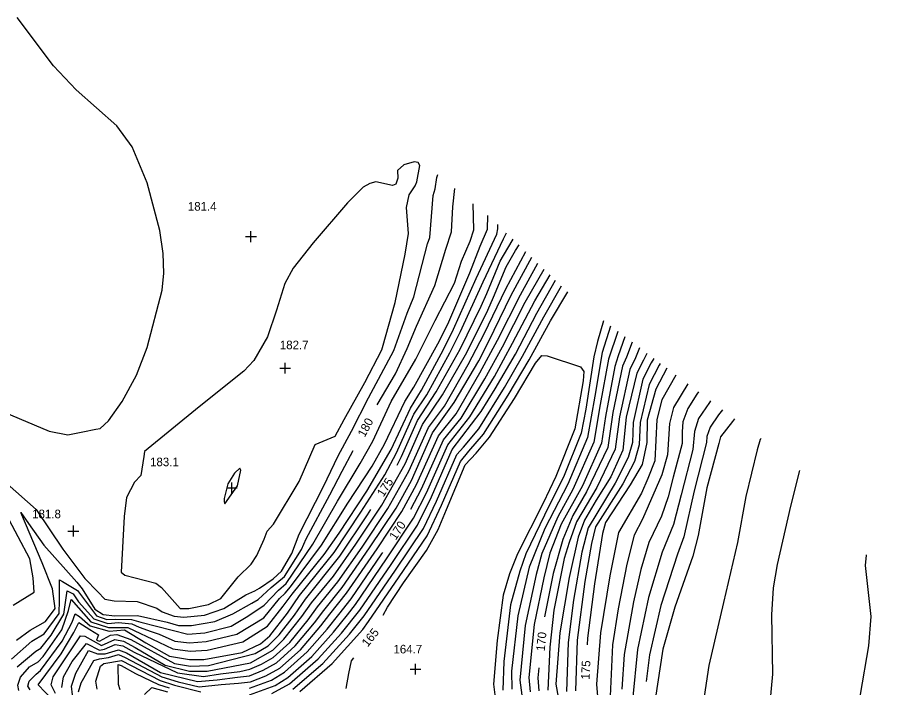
# Model space of a CAD drawing. Extents: x 1467615 to 2003689, y 770235 to 1108726.
# Drawn here: x 1996139.1 to 1996343.1, y 777293.4 to 777449.4 of the extents above; entities that cross this region are included whole.
import ezdxf

# ---------------------------------------------------------------- set-up
doc = ezdxf.new("R2010")
doc.units = 0
for name, color, linetype in [('RD_DTM_Major1', 7, 'Continuous'), ('RD_DTM_Major1_Lbl', 7, 'Continuous'), ('RD_DTM_Minor1', 7, 'Continuous'), ('RD_DTM_Spot_Elev', 7, 'Continuous')]:
    doc.layers.add(name, color=color, linetype=linetype)

msp = doc.modelspace()

# ---------------------------------------------------------------- linework, layer by layer
at = {"layer": 'RD_DTM_Major1'}
for points in [[(1996222.86, 777359.2), (1996227.12, 777366.41), (1996229.82, 777372.33), (1996232.01, 777377.55), (1996236.28, 777387.01), (1996238.85, 777395.49), (1996240.14, 777399.47), (1996240.48, 777405.34), (1996240.94, 777409.57)], [(1996227.5, 777345.19), (1996228.51, 777347.2), (1996232.22, 777355.58), (1996236.62, 777362.24), (1996242.21, 777372.2), (1996247.1, 777382.2), (1996248.39, 777385.16), (1996251.46, 777392.7), (1996254.3, 777397.39), (1996254.51, 777397.79)], [(1996230.66, 777334.93), (1996233.15, 777339.7), (1996238.31, 777351.1), (1996242.45, 777356.13), (1996247.89, 777365.3), (1996252.05, 777372.74), (1996257.34, 777383.14), (1996261.72, 777390.84)], [(1996282.2, 777373.79), (1996280.91, 777370.34), (1996280.01, 777368.24), (1996277.76, 777357.48), (1996276.53, 777349.26), (1996271.57, 777338.97), (1996268.39, 777333.49), (1996266.05, 777327.89), (1996263.83, 777320), (1996261.81, 777309.91)], [(1996224.26, 777310.25), (1996225.23, 777312.16), (1996228.95, 777317.79), (1996234.35, 777325.32), (1996237.07, 777330.21), (1996238.96, 777334.9), (1996243.38, 777345.26), (1996245.91, 777348.01), (1996249.03, 777351.7), (1996254.82, 777360.7), (1996259.69, 777368.92), (1996261.17, 777370.71), (1996262.43, 777370.63), (1996270.23, 777368.05), (1996270.98, 777366.96), (1996270.81, 777364.83), (1996268.89, 777353.65), (1996264.48, 777342.58), (1996261.54, 777336.34), (1996255.56, 777324.51), (1996253.68, 777319.91), (1996252.22, 777314.96), (1996250.81, 777304.36), (1996249.96, 777294.21), (1996250.44, 777290.47)], [(1996290.29, 777367.75), (1996287.7, 777362.89), (1996285.69, 777355.68), (1996285.66, 777350.46), (1996284.56, 777345.33), (1996281.76, 777340.61), (1996275.99, 777331.87), (1996275.29, 777329.29), (1996273.43, 777317.53), (1996271.8, 777304.94), (1996271.72, 777303.35)], [(1996303.26, 777358.07), (1996302.33, 777356.9), (1996300.37, 777354.06), (1996299.63, 777351.87), (1996299.56, 777350.49), (1996296.65, 777339.19), (1996294.29, 777328.5), (1996292.77, 777324.5), (1996288.94, 777312.53), (1996286.24, 777301.02), (1996285.48, 777294.83)], [(1996138.87, 777304.46), (1996142.07, 777306.78), (1996145.61, 777308.78), (1996147.84, 777311.79), (1996147.28, 777316.41), (1996144.82, 777322.48), (1996140.95, 777331.57), (1996139.89, 777334.15), (1996141.64, 777331.59), (1996145.21, 777326.58), (1996152.93, 777317.94), (1996154.16, 777316.4), (1996157.11, 777311.65), (1996159.03, 777310.4), (1996161.76, 777310.12), (1996167.05, 777310.17), (1996173.99, 777308.65), (1996176.56, 777307.88), (1996179.66, 777307.88), (1996185.08, 777308.81), (1996189.21, 777310.57), (1996193.64, 777313.03), (1996195.18, 777313.94), (1996198.19, 777316.7), (1996201.24, 777319.28), (1996205.26, 777325.52), (1996206.34, 777328), (1996211.85, 777338.26), (1996214.69, 777343.8), (1996217.24, 777348.59)], [(1996150.46, 777287.23), (1996143.91, 777294.05), (1996149.27, 777301.28), (1996152.21, 777306.22), (1996153.39, 777308.57), (1996155.91, 777306.91), (1996157.93, 777305.71), (1996157.47, 777304.43), (1996158.22, 777304.19), (1996160.73, 777305.64), (1996162.2, 777305.75), (1996165.52, 777304.64), (1996175.68, 777299.03), (1996179.36, 777298.41), (1996183.57, 777298.53), (1996194.42, 777301.34), (1996197.47, 777303.1), (1996200.06, 777305.67), (1996203.6, 777310.29), (1996206.16, 777313.99), (1996214.13, 777323.97), (1996220.57, 777333.62), (1996221.37, 777334.87)], [(1996193.16, 777293.24), (1996198.26, 777295.12), (1996201.27, 777296.97), (1996206.58, 777301.73), (1996211.21, 777307.03), (1996213.92, 777310.45), (1996216.76, 777314.07), (1996223.95, 777324.53), (1996224.16, 777324.85)], [(1996215.66, 777293.23), (1996216.22, 777296.66), (1996216.85, 777299.62), (1996217.44, 777300.34)], [(1996157.66, 777293.03), (1996157.36, 777294.87), (1996158.4, 777298.4), (1996159.17, 777299), (1996163.35, 777299.69), (1996172.32, 777295.03), (1996175.67, 777293.96), (1996181.76, 777292.44)], [(1996260.47, 777297.98), (1996260.24, 777295.65), (1996260.53, 777292.62)]]:
    msp.add_lwpolyline(points, dxfattribs=at)
at = {"layer": 'RD_DTM_Minor1'}
for points in [[(1996136, 777357.5), (1996146.46, 777353.11), (1996150.83, 777352.27), (1996154.33, 777352.98), (1996157.36, 777353.55), (1996158.33, 777353.73), (1996160.31, 777355.49), (1996163.51, 777359.98), (1996166.84, 777366.12), (1996169.26, 777372.54), (1996172.77, 777385.89), (1996173.18, 777389.88), (1996173.05, 777394.49), (1996172.26, 777399.81), (1996169.32, 777410.89), (1996165.82, 777419.27), (1996162.21, 777424.21), (1996152.77, 777432.55), (1996147.5, 777438.16), (1996139.05, 777449.39)], [(1996224.07, 777372.61), (1996227.05, 777383.05), (1996229.4, 777394.28), (1996230.12, 777399.12), (1996229.68, 777405.15), (1996230.3, 777408.08), (1996231.73, 777410.21), (1996232.08, 777411.17), (1996232.77, 777414.95), (1996232.37, 777415.65), (1996231.47, 777415.83), (1996229.07, 777415.09), (1996227.62, 777413.8), (1996227.64, 777411.98), (1996227.18, 777410.56), (1996226.43, 777410.32), (1996222.51, 777411.12), (1996221.18, 777410.77), (1996219.63, 777409.88), (1996215.94, 777406.28), (1996207.96, 777396.92), (1996203.33, 777391.03), (1996201.34, 777387.44), (1996199.39, 777381.27), (1996197.31, 777375.04), (1996194.13, 777369.52), (1996191.83, 777367.09), (1996181.42, 777358.74), (1996168.7, 777348.36), (1996168.52, 777347.18), (1996167.81, 777342.81), (1996166.38, 777341.21), (1996164.49, 777337.69), (1996163.91, 777333.24), (1996163.27, 777320.3), (1996164.1, 777319.6), (1996171.35, 777317.7), (1996172.66, 777316.68), (1996176.97, 777311.85), (1996178.97, 777311.82), (1996183.59, 777312.74), (1996186.44, 777314.15), (1996188.31, 777316.44), (1996190.51, 777319.21), (1996193.51, 777322.11), (1996194.87, 777324.13), (1996196.57, 777327.97), (1996197.24, 777329.82), (1996198.7, 777331.47), (1996204.7, 777341.37), (1996208.44, 777349.99), (1996213.07, 777351.95), (1996215.16, 777355.84), (1996220.01, 777364.43), (1996223.91, 777372.06), (1996224.07, 777372.61)], [(1996136.72, 777340.87), (1996143.49, 777334.84), (1996149.66, 777325.67), (1996154.81, 777318.84), (1996157.84, 777315.68), (1996159.42, 777314.01), (1996161.62, 777313.59), (1996166.96, 777313.47), (1996171.55, 777311.91), (1996172.81, 777311.04), (1996175.58, 777310.04), (1996177.86, 777309.78), (1996182.68, 777310.26), (1996187.12, 777311.86), (1996192.3, 777314.99), (1996194.33, 777315.9), (1996195.44, 777316.55), (1996198.62, 777318.72), (1996200.56, 777320.54), (1996203, 777324.6), (1996204.67, 777329.13), (1996210.35, 777340.2), (1996212.07, 777343.82), (1996213.76, 777347.36), (1996216.9, 777353.12), (1996220.83, 777360.83), (1996226.74, 777371.87), (1996229.83, 777380.56), (1996231.38, 777384.38), (1996234.6, 777396.7), (1996235.08, 777398.2), (1996235.86, 777407.93), (1996236.35, 777409.48), (1996236.77, 777412.14), (1996236.95, 777412.85)], [(1996137.74, 777300.01), (1996142.44, 777304.23), (1996145.33, 777305.95), (1996148.81, 777310.69), (1996148.87, 777313.73), (1996148.85, 777318.53), (1996149.58, 777318.11), (1996153.04, 777315.98), (1996157.52, 777310.11), (1996159.89, 777309.27), (1996161.95, 777309.32), (1996165.65, 777309.26), (1996167.83, 777308.65), (1996178.78, 777305.85), (1996182.74, 777306.14), (1996188.85, 777307.7), (1996192.73, 777310.07), (1996196.57, 777312.61), (1996199.91, 777316.1), (1996201.65, 777317.66), (1996207.87, 777326.82), (1996213.62, 777336.78), (1996218.92, 777345.57), (1996221.88, 777350.81), (1996226.09, 777359.99), (1996231.84, 777369.87), (1996236.37, 777378.84), (1996240.87, 777387.54), (1996242.52, 777392.64), (1996244.53, 777397.36), (1996245.33, 777399.95), (1996245.23, 777406.05)], [(1996139, 777298.25), (1996143.38, 777301.92), (1996144.51, 777302.56), (1996146.94, 777305.58), (1996149.86, 777310.53), (1996150.68, 777315.92), (1996152.08, 777315.26), (1996153.3, 777313.39), (1996156.85, 777309.41), (1996160.13, 777308.3), (1996162.63, 777308.55), (1996165.72, 777308.23), (1996167.42, 777307.49), (1996170.26, 777306.46), (1996172.13, 777305.86), (1996175.74, 777304.25), (1996179.19, 777303.86), (1996183.01, 777304.13), (1996190.16, 777305.86), (1996196.49, 777309.66), (1996200.13, 777314.16), (1996201.42, 777315.36), (1996202.69, 777316.85), (1996209.88, 777326.53), (1996216.04, 777336.32), (1996221.66, 777344.93), (1996224.53, 777350.09), (1996229.3, 777360.03), (1996231.4, 777363.38), (1996236.98, 777373.46), (1996239.27, 777378.03), (1996244.43, 777389.93), (1996246.86, 777396.2), (1996248.57, 777400.09), (1996248.6, 777403.28)], [(1996139.44, 777292.7), (1996139.15, 777293.94), (1996139.77, 777295.86), (1996141.88, 777298.21), (1996143.9, 777299.43), (1996145.06, 777300.63), (1996149.4, 777306.83), (1996151.02, 777311.35), (1996151.63, 777313.94), (1996156.18, 777308.71), (1996160.29, 777307.38), (1996164.81, 777307.43), (1996171.98, 777304.01), (1996175.24, 777302.47), (1996179.34, 777301.88), (1996183.27, 777302.12), (1996191.55, 777304.08), (1996197.35, 777307.72), (1996200.99, 777312.38), (1996203.06, 777315.15), (1996210.51, 777324.42), (1996213.99, 777329.39), (1996220.42, 777339.14), (1996226.13, 777348.85), (1996230.59, 777358.47), (1996233.2, 777362.68), (1996238.26, 777372.1), (1996240.64, 777376.86), (1996245.88, 777388.65), (1996250.68, 777398.94), (1996250.94, 777400.23), (1996250.94, 777401.23)], [(1996142.03, 777292.88), (1996141.53, 777293.74), (1996141.83, 777294.94), (1996143.42, 777296.53), (1996144.48, 777297.37), (1996149.51, 777304.2), (1996151.81, 777308.64), (1996152.54, 777310.6), (1996153.52, 777309.97), (1996156, 777307.81), (1996160.47, 777306.53), (1996164.03, 777306.83), (1996168.96, 777303.8), (1996174.52, 777300.75), (1996179.14, 777299.94), (1996182.53, 777299.97), (1996191.4, 777301.59), (1996195.67, 777303.6), (1996197.86, 777305.42), (1996201.99, 777310.76), (1996204.74, 777314.86), (1996212.82, 777324.85), (1996219.05, 777334.22), (1996224.67, 777342.94), (1996227.32, 777348.04), (1996231.41, 777357.03), (1996234.42, 777361.52), (1996239.78, 777371.36), (1996242.27, 777376.27), (1996247.52, 777387.86), (1996252.27, 777397.84), (1996252.97, 777399.27)], [(1996147.92, 777292.01), (1996146.93, 777294.08), (1996147.43, 777295.91), (1996153.74, 777305.42), (1996154.8, 777305.4), (1996158.65, 777303.22), (1996161.76, 777304.63), (1996163.81, 777304.21), (1996166.52, 777302.73), (1996173.52, 777298.62), (1996179.18, 777297.26), (1996183.25, 777297.27), (1996193.33, 777299.21), (1996198.56, 777302.13), (1996201.14, 777304.65), (1996205.3, 777309.94), (1996207.57, 777313.11), (1996212.66, 777319.35), (1996217.91, 777326.77), (1996223.97, 777335.88), (1996229.36, 777345.48), (1996233.4, 777354.64), (1996238.08, 777361.52), (1996243.7, 777371.38), (1996248.63, 777381.29), (1996249.96, 777384.31), (1996252.91, 777391.34), (1996255.04, 777395.14), (1996255.88, 777396.47)], [(1996149.46, 777293.43), (1996149.85, 777295.89), (1996151.84, 777299.48), (1996155.2, 777303.71), (1996158.19, 777302.13), (1996159.34, 777302.39), (1996161.84, 777303.45), (1996163.6, 777303.13), (1996166.29, 777301.64), (1996176.35, 777296.88), (1996182.4, 777296.03), (1996186.38, 777296.65), (1996190.84, 777297.14), (1996193.19, 777297.67), (1996195.94, 777298.85), (1996198.67, 777300.4), (1996202.48, 777303.91), (1996206.78, 777309.21), (1996208.98, 777312.24), (1996213.69, 777318.03), (1996219.34, 777326.09), (1996225.35, 777335.1), (1996230.2, 777343.79), (1996234.78, 777353.96), (1996238.51, 777358.94), (1996244.03, 777368.62), (1996247.75, 777375.76), (1996252.8, 777386.23), (1996257.5, 777394.9)], [(1996151.89, 777291.74), (1996151.68, 777293.74), (1996152.7, 777296.8), (1996155.61, 777302.02), (1996157.77, 777301.24), (1996159.51, 777301.29), (1996162.66, 777302.22), (1996164.49, 777301.51), (1996172.44, 777296.93), (1996181.03, 777294.81), (1996185.6, 777295.23), (1996190.31, 777295.8), (1996193.11, 777296.17), (1996196.31, 777297.43), (1996199.42, 777299.17), (1996203.74, 777303.1), (1996208.25, 777308.48), (1996210.4, 777311.36), (1996214.71, 777316.71), (1996221.1, 777325.92), (1996227.24, 777335.19), (1996230.82, 777341.62), (1996235.76, 777352.75), (1996240.81, 777359.79), (1996246.51, 777369.49), (1996248.79, 777373.92), (1996254.06, 777384.72), (1996258.83, 777393.62)], [(1996153.28, 777292.41), (1996153.94, 777294.52), (1996156.88, 777299.7), (1996158.23, 777300.11), (1996160.28, 777300.44), (1996162.65, 777301.08), (1996164.16, 777300.45), (1996172.7, 777295.9), (1996176.52, 777294.76), (1996181.41, 777293.62), (1996186.53, 777294.15), (1996190.54, 777294.45), (1996193.36, 777294.77), (1996196.95, 777296.13), (1996200.18, 777297.95), (1996204.98, 777302.23), (1996209.73, 777307.76), (1996211.81, 777310.49), (1996215.74, 777315.39), (1996222.84, 777325.7), (1996228.6, 777334.4), (1996231.99, 777340.66), (1996237.14, 777352.05), (1996241.21, 777357.17), (1996246.77, 777366.66), (1996250.89, 777374.31), (1996256.19, 777384.85), (1996260.28, 777392.22)], [(1996193.11, 777291.76), (1996199.08, 777293.91), (1996202.02, 777295.75), (1996207.63, 777300.67), (1996212.69, 777306.31), (1996215.96, 777310.34), (1996217.79, 777312.75), (1996225.06, 777323.36), (1996231.33, 777332.81), (1996234.31, 777338.74), (1996239.3, 777349.93), (1996244.46, 777356.42), (1996250.18, 777365.82), (1996254.37, 777373.55), (1996259.57, 777383.47), (1996263.12, 777389.48)], [(1996198.36, 777292.01), (1996202.46, 777294.27), (1996209.14, 777300.07), (1996214.53, 777306.08), (1996218.81, 777311.43), (1996226.12, 777322.1), (1996232.24, 777331.2), (1996235.47, 777337.78), (1996240.34, 777348.81), (1996247.06, 777357.7), (1996250.33, 777362.95), (1996255.05, 777371.04), (1996260.06, 777380.54), (1996264.38, 777388.27)], [(1996203.21, 777293.04), (1996210.24, 777299.04), (1996216.42, 777305.82), (1996219.84, 777310.11), (1996227.09, 777320.71), (1996233.62, 777330.42), (1996236.64, 777336.82), (1996241.38, 777347.67), (1996242.95, 777349.35), (1996246.55, 777353.68), (1996252.5, 777363.23), (1996256.73, 777370.56), (1996261.65, 777379.68), (1996265.79, 777386.91)], [(1996204.86, 777292.52), (1996212.36, 777299.04), (1996219.52, 777306.9), (1996220.86, 777308.79), (1996228, 777319.23), (1996234.52, 777328.73), (1996237.8, 777335.86), (1996242.22, 777346.03), (1996244.19, 777348.44), (1996247.61, 777352.42), (1996253.32, 777361.45), (1996258.21, 777369.74), (1996263.24, 777378.82), (1996267.23, 777385.52)], [(1996275.52, 777378.78), (1996274.13, 777373.99), (1996273.3, 777370.38), (1996271.44, 777358.21), (1996270.35, 777352.62), (1996266.21, 777342.38), (1996262.91, 777335.77), (1996257.43, 777324.56), (1996256.04, 777320.48), (1996253.9, 777312.64), (1996252.32, 777299.52), (1996252.13, 777292.79)], [(1996277.17, 777377.55), (1996275.24, 777371.44), (1996273.51, 777361.26), (1996271.81, 777351.59), (1996267.28, 777340.77), (1996261.91, 777330.41), (1996258.28, 777321.43), (1996255.6, 777310.14), (1996254.16, 777297.23), (1996254.18, 777293.02)], [(1996278.86, 777376.28), (1996276.74, 777369.88), (1996274.81, 777359.29), (1996273.27, 777350.56), (1996268.38, 777339.54), (1996264.91, 777333.15), (1996261.17, 777324.66), (1996259.87, 777319.71), (1996257.35, 777307.88), (1996256.11, 777295.17), (1996256.52, 777291.62)], [(1996280.51, 777375.05), (1996278.93, 777370.67), (1996278.2, 777368.16), (1996276.04, 777356.55), (1996275.06, 777350.28), (1996270.65, 777340.39), (1996265.73, 777331.44), (1996263.03, 777324.71), (1996261.69, 777318.96), (1996259.41, 777308.06), (1996258.18, 777295.73), (1996258.46, 777292.4)], [(1996283.92, 777372.5), (1996283, 777370.18), (1996281.65, 777367.42), (1996279.25, 777356.42), (1996278.3, 777348.91), (1996274.02, 777340.01), (1996269.3, 777332), (1996267.57, 777327.17), (1996266.43, 777323.44), (1996263.95, 777311.47), (1996263.03, 777302.81), (1996262.6, 777292.84)], [(1996285.66, 777371.2), (1996284.83, 777369.6), (1996283.28, 777366.6), (1996280.86, 777356.36), (1996280.09, 777348.69), (1996277.27, 777342.49), (1996273.85, 777337.06), (1996271.12, 777332.36), (1996269.66, 777328.46), (1996267.53, 777319.04), (1996265.37, 777306.19), (1996264.44, 777294.21), (1996266.44, 777282.94)], [(1996287.24, 777370.03), (1996286.67, 777369.01), (1996284.73, 777365.2), (1996282.46, 777355.11), (1996282.28, 777350.49), (1996281.3, 777346.98), (1996278.3, 777341.01), (1996271.99, 777330.62), (1996270.5, 777324.91), (1996268.58, 777313.77), (1996267.29, 777303.92), (1996266.93, 777292.5)], [(1996288.78, 777368.88), (1996288.5, 777368.43), (1996286.21, 777363.97), (1996284.09, 777355.1), (1996283.89, 777349.95), (1996282.8, 777346.02), (1996280.02, 777340.82), (1996273.7, 777330.84), (1996272.79, 777326.95), (1996271.23, 777318.09), (1996269.43, 777304.47), (1996269.01, 777292.67)], [(1996292.41, 777366.17), (1996289.12, 777360.38), (1996287.98, 777355.79), (1996287.47, 777346.21), (1996285.87, 777342.05), (1996284.4, 777338.65), (1996279.07, 777329.54), (1996277.04, 777319.39), (1996274.86, 777306.16), (1996273.91, 777294.17), (1996274.61, 777285.71)], [(1996295.16, 777364.12), (1996291.84, 777358.61), (1996290.9, 777354.86), (1996290.45, 777347.6), (1996289.17, 777342.96), (1996284.62, 777332.65), (1996282.68, 777328.89), (1996281.02, 777322.17), (1996278.98, 777311.78), (1996277.63, 777303.37), (1996277.1, 777291.42)], [(1996297.69, 777362.22), (1996297.31, 777361.68), (1996295.21, 777358.37), (1996294.06, 777355.3), (1996293.85, 777352.92), (1996293.84, 777350.26), (1996291.81, 777342.37), (1996290.62, 777337.83), (1996289.08, 777333.33), (1996286.09, 777327.18), (1996284.23, 777320.92), (1996282.54, 777313.34), (1996280.37, 777301.11), (1996279.83, 777293.06)], [(1996300.49, 777360.13), (1996300.25, 777359.79), (1996297.69, 777356.02), (1996296.72, 777353), (1996296.33, 777348.84), (1996293.62, 777338.31), (1996291.84, 777331.36), (1996289.21, 777324.96), (1996286.06, 777314.42), (1996283.44, 777302.28), (1996282.32, 777290.46), (1996282.2, 777286.72), (1996282.52, 777275.7), (1996282.69, 777269.52), (1996281.67, 777262.98), (1996281.74, 777258.09), (1996282.62, 777247.02), (1996283.61, 777241.19), (1996285.5, 777233.85), (1996290.96, 777225.06), (1996298.49, 777216.22), (1996306.51, 777206.21), (1996309.04, 777203.23)], [(1996306.07, 777355.97), (1996305.6, 777355.35), (1996302.83, 777351.75), (1996302.37, 777350.25), (1996299.59, 777339.88), (1996297.63, 777328.83), (1996296.33, 777324.04), (1996292.14, 777312.13), (1996289.35, 777302.36), (1996287.61, 777290.61), (1996287.26, 777286.7), (1996287.46, 777279.6), (1996288.56, 777266.31), (1996288.35, 777260.59), (1996289.12, 777250.46), (1996291.97, 777237.98), (1996296.43, 777228.86), (1996300.9, 777223.38), (1996309.4, 777213.36), (1996313.4, 777208.54)], [(1996312.25, 777351.36), (1996312.05, 777351.13), (1996311.3, 777348.74), (1996308.72, 777337.91), (1996306.72, 777327.22), (1996303.53, 777313.24), (1996300.07, 777298.57), (1996298.54, 777288.27), (1996297.15, 777276.41), (1996297.22, 777271.68), (1996296.25, 777264.8), (1996295.76, 777255.07), (1996294.02, 777246.82), (1996295.27, 777240.03), (1996296.5, 777236.89), (1996299.25, 777230.94), (1996302.06, 777227), (1996309.47, 777218.39), (1996315.55, 777211.16)], [(1996187.2, 777336.72), (1996187.4, 777336.15), (1996190.33, 777340.41), (1996191.09, 777344.06), (1996190.9, 777344.48), (1996189.6, 777343.35), (1996188.08, 777340.82), (1996187.24, 777337.44), (1996187.2, 777336.72)], [(1996321.22, 777343.95), (1996319.06, 777335.63), (1996316.02, 777322.03), (1996315.02, 777316.64), (1996314.67, 777310.32), (1996314.89, 777296.51), (1996313.94, 777286.5), (1996312.74, 777274.55), (1996313.24, 777264.99), (1996313.68, 777256.51), (1996313.07, 777251.95), (1996311.42, 777248.14), (1996308.34, 777242.34), (1996305.21, 777232.21), (1996305.15, 777230.15), (1996306.99, 777227.47), (1996314.34, 777218.97), (1996318.41, 777214.65)], [(1996138.1, 777312.62), (1996142.98, 777315.63), (1996142.76, 777318.94), (1996141.94, 777323.35), (1996136.55, 777333.59)], [(1996336.72, 777324.29), (1996336.71, 777324.26), (1996336.49, 777321.82), (1996337.77, 777309.99), (1996337.23, 777303.15), (1996335.33, 777291.77), (1996334.97, 777284.71), (1996335.56, 777281.83), (1996337.82, 777277.19), (1996341.17, 777271.3), (1996342.52, 777266.11), (1996343.07, 777258.67), (1996342.52, 777250.58), (1996340.31, 777241.32)], [(1996163.05, 777292.87), (1996162.59, 777294.12), (1996162.56, 777298.77), (1996163.22, 777298.59), (1996166.57, 777296.67), (1996171.94, 777294.15), (1996174.4, 777293.32)], [(1996168.67, 777291.78), (1996170.4, 777293.46), (1996174.06, 777292.39)]]:
    msp.add_lwpolyline(points, dxfattribs=at)
at = {"layer": 'RD_DTM_Spot_Elev'}
for p, q in [((1996192.22, 777398.38), (1996194.72, 777398.38)), ((1996193.47, 777397.13), (1996193.47, 777399.63)), ((1996200.21, 777367.79), (1996202.71, 777367.79)), ((1996201.46, 777366.54), (1996201.46, 777369.04)), ((1996188.99, 777338.68), (1996188.99, 777341.18)), ((1996187.74, 777339.93), (1996190.24, 777339.93)), ((1996152.11, 777328.61), (1996152.11, 777331.11)), ((1996150.86, 777329.86), (1996153.36, 777329.86)), ((1996231.79, 777296.46), (1996231.79, 777298.96)), ((1996230.54, 777297.71), (1996233.04, 777297.71))]:
    msp.add_line(p, q, dxfattribs=at)

# ---------------------------------------------------------------- texts
at = {"layer": 'RD_DTM_Major1_Lbl'}
for s, rotation, p in [('180', 61.9405, (1996219.95, 777351.53)), ('175', 57.4794, (1996224.32, 777337.64)), ('170', 56.4508, (1996227.17, 777327.59)), ('165', 51.2395, (1996220.64, 777302.73)), ('170', 84.3809, (1996261.85, 777301.81)), ('175', 87.0766, (1996272.3, 777295.23))]:
    msp.add_text(s, height=2, rotation=rotation, dxfattribs=at).set_placement(p)
at = {"layer": 'RD_DTM_Spot_Elev'}
for s, p in [('181.4', (1996178.77, 777404.43)), ('182.7', (1996200.19, 777372.17)), ('183.1', (1996169.97, 777344.94)), ('181.8', (1996142.52, 777332.83)), ('164.7', (1996226.64, 777301.36))]:
    msp.add_text(s, height=2, dxfattribs=at).set_placement(p)

doc.saveas('drawing.dxf')
